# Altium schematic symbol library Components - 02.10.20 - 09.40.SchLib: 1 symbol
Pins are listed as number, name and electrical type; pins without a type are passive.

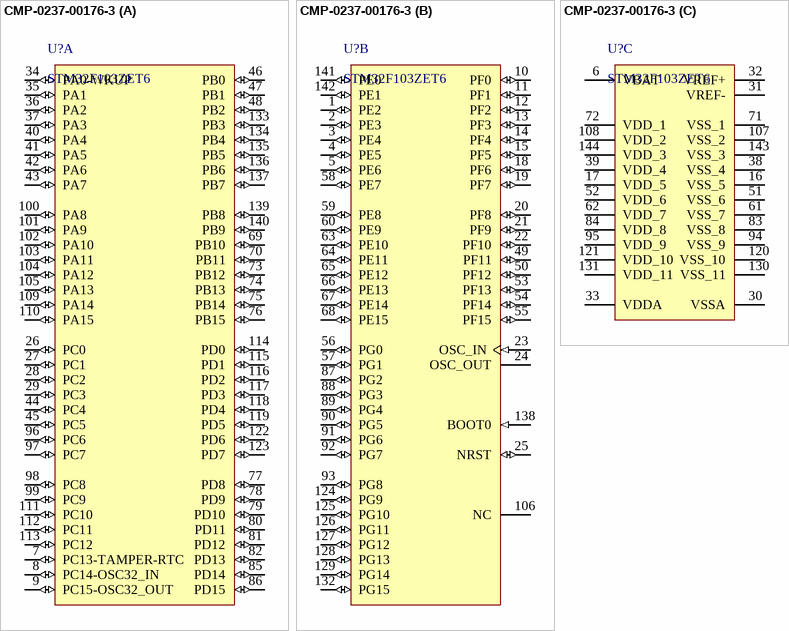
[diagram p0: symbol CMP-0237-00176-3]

## CMP-0237-00176-3
designator U?, comment STM32F103ZET6
ARM Cortex-M3 32-bit MCU, 512 KB Flash, 64 KB Internal RAM, 112 I/Os, 144-pin LQFP, -40 to 85 degC, Tray; D/A Converter: 2x12-bit (2 Channel); FLASH Size (Prog) (kB): 512; Internal RAM Size (kB): 64; I/Os (High Current): 112; Supply Voltage(Vcc) min (V): 2; Operating Frequency(F) (Processor speed) (MHz): 72; A/D Converter: 3x12-bit (21 Channel)
footprint STM-LQFP144_L (Thin QFP, 144-Leads, Body 20x20mm, Pitch 0.5mm, IPC High Density)
footprint STM-LQFP144_M (Thin QFP, 144-Leads, Body 20x20mm, Pitch 0.5mm, IPC Low Density)
footprint STM-LQFP144_N (Thin QFP, 144-Leads, Body 20x20mm, Pitch 0.5mm, IPC Medium Density)
footprint STM-LQFP144_V (Thin QFP, 144-Leads, Body 20x20mm, Pitch 0.5mm, ST Recommended)
part A pins: 7 PC13-TAMPER-RTC (io) "PC13-TAMPER-RTC/PC13/TAMPER-RTC", 8 PC14-OSC32_IN (io) "PC14-OSC32_IN/PC14/OSC32_IN", 9 PC15-OSC32_OUT (io) "PC15-OSC32_OUT/PC15/OSC32_OUT", 26 PC0 (io) "PC0/ADC123_IN10", 27 PC1 (io) "PC1/ADC123_IN11", 28 PC2 (io) "PC2/ADC123_IN12", 29 PC3 (io) "PC3/ADC123_IN13", 34 PA0-WKUP (io) "PA0-WKUP/PA0/WKUP/USART2_CTS/ADC123_IN0/TIM2_CH1_ETR/TIM5_CH1/TIM8_ETR", 35 PA1 (io) "PA1/USART2_RTS/ADC123_IN1/TIM5_CH2/TIM2_CH2", 36 PA2 (io) "PA2/USART2_TX/TIM5_CH3/ADC123_IN2/TIM2_CH3", 37 PA3 (io) "PA3/USART2_RX/TIM5_CH4/ADC123_IN3/TIM2_CH4", 40 PA4 (io) "PA4/SPI1_NSS/USART2_CK/DAC_OUT1/ADC12_IN4", 41 PA5 (io) "PA5/SPI1_SCK/DAC_OUT2/ADC12_IN5", 42 PA6 (io) "PA6/SPI1_MISO/TIM8_BKIN/ADC12_IN6/TIM3_CH1/TIM1_BKIN", 43 PA7 (io) "PA7/SPI1_MOSI/TIM8_CH1N/ADC12_IN7/TIM3_CH2/TIM1_CH1N", 44 PC4 (io) "PC4/ADC12_IN14", 45 PC5 (io) "PC5/ADC12_IN15", 46 PB0 (io) "PB0/ADC12_IN8/TIM3_CH3/TIM8_CH2N/TIM1_CH2N", 47 PB1 (io) "PB1/ADC12_IN9/TIM3_CH4/TIM8_CH3N/TIM1_CH3N", 48 PB2 (io) "PB2/BOOT1", 69 PB10 (io) "PB10/I2C2_SCL/USART3_TX/TIM2_CH3", 70 PB11 (io) "PB11/I2C2_SDA/USART3_RX/TIM2_CH4", 73 PB12 (io) "PB12/SPI2_NSS/I2S2_WS/I2C2_SMBA/USART3_CK/TIM1_BKIN", 74 PB13 (io) "PB13/SPI2_SCK/I2S2_CK/USART3_CTS/TIM1_CH1N", 75 PB14 (io) "PB14/SPI2_MISO/TIM1_CH2N/USART3_RTS", 76 PB15 (io) "PB15/SPI2_MOSI/I2S2_SD/TIM1_CH3N", 77 PD8 (io) "PD8/FSMC_D13/USART3_TX", 78 PD9 (io) "PD9/FSMC_D14/USART3_RX", 79 PD10 (io) "PD10/FSMC_D15/USART3_CK", 80 PD11 (io) "PD11/FSMC_A16/USART3_CTS", 81 PD12 (io) "PD12/FSMC_A17/TIM4_CH1/USART3_RTS", 82 PD13 (io) "PD13/FSMC_A18/TIM4_CH2", 85 PD14 (io) "PD14/FSMC_D0/TIM4_CH3", 86 PD15 (io) "PD15/FSMC_D1/TIM4_CH4", 96 PC6 (io) "PC6/I2S2_MCK/TIM8_CH1/SDIO_D6/TIM3_CH1", 97 PC7 (io) "PC7/I2S3_MCK/TIM8_CH2/SDIO_D7/TIM3_CH2", 98 PC8 (io) "PC8/TIM8_CH3/SDIO_D0/TIM3_CH3", 99 PC9 (io) "PC9/TIM8_CH4/SDIO_D1/TIM3_CH4", 100 PA8 (io) "PA8/USART1_CK/TIM1_CH1/MCO", 101 PA9 (io) "PA9/USART1_TX/TIM1_CH2", 102 PA10 (io) "PA10/USART1_RX/TIM1_CH3", 103 PA11 (io) "PA11/USART1_CTS/USBDM/CAN_RX/TIM1_CH4", 104 PA12 (io) "PA12/USART1_RTS/USBDP/CAN_TX/TIM1_ETR", 105 PA13 (io) "PA13/JTMS-SWDIO", 109 PA14 (io) "PA14/JTCK-SWCLK", 110 PA15 (io) "PA15/JTDI/SPI3_NSS/I2S3_WS/TIM2_CH1_ETR/SPI1_NSS", 111 PC10 (io) "PC10/UART4_TX/SDIO_D2/USART3_TX", 112 PC11 (io) "PC11/UART4_RX/SDIO_D3/USART3_RX", 113 PC12 (io) "PC12/UART5_TX/SDIO_CK/USART3_CK", 114 PD0 (io) "PD0/OSC_IN/FSMC_D2/CAN_RX", 115 PD1 (io) "PD1/OSC_OUT/FSMC_D3/CAN_TX", 116 PD2 (io) "PD2/TIM3_ETR/UART5_RX/SDIO_CMD", 117 PD3 (io) "PD3/FSMC_CLK/USART2_CTS", 118 PD4 (io) "PD4/FSMC_NOE/USART2_RTS", 119 PD5 (io) "PD5/FSMC_NWE/USART2_TX", 122 PD6 (io) "PD6/FSMC_NWAIT/USART2_RX", 123 PD7 (io) "PD7/FSMC_NE1/FSMC_NCE2/USART2_CK", 133 PB3 (io) "PB3/JTDO/SPI3_SCK/I2S3_CK/TRACESWO/TIM2_CH2/SPI1_SCK", 134 PB4 (io) "PB4/NJTRST/SPI3_MISO/TIM3_CH1/SPI1_MISO", 135 PB5 (io) "PB5/I2C1_SMBA/SPI3_MOSI/I2S3_SD/TIM3_CH2/SPI1_MOSI", 136 PB6 (io) "PB6/I2C1_SCL/TIM4_CH1/USART1_TX", 137 PB7 (io) "PB7/I2C1_SDA/FSMC_NADV/TIM4_CH2/USART1_RX", 139 PB8 (io) "PB8/TIM4_CH3/SDIO_D4/I2C1_SCL/CAN_RX", 140 PB9 (io) "PB9/TIM4_CH4/SDIO_D5/I2C1_SDA/CAN_TX"
part B pins: 1 PE2 (io) "PE2/TRACECK/FSMC_A23", 2 PE3 (io) "PE3/TRACED0/FSMC_A19", 3 PE4 (io) "PE4/TRACED1/FSMC_A20", 4 PE5 (io) "PE5/TRACED2/FSMC_A21", 5 PE6 (io) "PE6/TRACED3/FSMC_A22", 10 PF0 (io) "PF0/FSMC_A0", 11 PF1 (io) "PF1/FSMC_A1", 12 PF2 (io) "PF2/FSMC_A2", 13 PF3 (io) "PF3/FSMC_A3", 14 PF4 (io) "PF4/FSMC_A4", 15 PF5 (io) "PF5/FSMC_A5", 18 PF6 (io) "PF6/ADC3_IN4/FSMC_NIORD", 19 PF7 (io) "PF7/ADC3_IN5/FSMC_NREG", 20 PF8 (io) "PF8/ADC3_IN6/FSMC_NIOWR", 21 PF9 (io) "PF9/ADC3_IN7/FSMC_CD", 22 PF10 (io) "PF10/ADC3_IN8/FSMC_INTR", 23 OSC_IN (in), 24 OSC_OUT, 25 NRST (io), 49 PF11 (io) "PF11/FSMC_NIOS16", 50 PF12 (io) "PF12/FSMC_A6", 53 PF13 (io) "PF13/FSMC_A7", 54 PF14 (io) "PF14/FSMC_A8", 55 PF15 (io) "PF15/FSMC_A9", 56 PG0 (io) "PG0/FSMC_A10", 57 PG1 (io) "PG1/FSMC_A11", 58 PE7 (io) "PE7/FSMC_D4/TIM1_ETR", 59 PE8 (io) "PE8/FSMC_D5/TIM1_CH1N", 60 PE9 (io) "PE9/FSMC_D6/TIM1_CH1", 63 PE10 (io) "PE10/FSMC_D7/TIM1_CH2N", 64 PE11 (io) "PE11/FSMC_D8/TIM1_CH2", 65 PE12 (io) "PE12/FSMC_D9/TIM1_CH3N", 66 PE13 (io) "PE13/FSMC_D10/TIM1_CH3", 67 PE14 (io) "PE14/FSMC_D11/TIM1_CH4", 68 PE15 (io) "PE15/FSMC_D12/TIM1_BKIN", 87 PG2 (io) "PG2/FSMC_A12", 88 PG3 (io) "PG3/FSMC_A13", 89 PG4 (io) "PG4/FSMC_A14", 90 PG5 (io) "PG5/FSMC_A15", 91 PG6 (io) "PG6/FSMC_INT2", 92 PG7 (io) "PG7/FSMC_INT3", 93 PG8 (io), 106 NC, 124 PG9 (io) "PG9/FSMC_NE2/FSMC_NCE3", 125 PG10 (io) "PG10/FSMC_NCE4_1/FSMC_NE3", 126 PG11 (io) "PG11/FSMC_NCE4_2", 127 PG12 (io) "PG12/FSMC_NE4", 128 PG13 (io) "PG13/FSMC_A24", 129 PG14 (io) "PG14/FSMC_A25", 132 PG15 (io), 138 BOOT0 (in), 141 PE0 (io) "PE0/TIM4_ETR/FSMC_NBL0", 142 PE1 (io) "PE1/FSMC_NBL1"
part C pins: 6 VBAT (power), 16 VSS_5 (power), 17 VDD_5 (power), 30 VSSA (power), 31 VREF- (power), 32 VREF+ (power), 33 VDDA (power), 38 VSS_4 (power), 39 VDD_4 (power), 51 VSS_6 (power), 52 VDD_6 (power), 61 VSS_7 (power), 62 VDD_7 (power), 71 VSS_1 (power), 72 VDD_1 (power), 83 VSS_8 (power), 84 VDD_8 (power), 94 VSS_9 (power), 95 VDD_9 (power), 107 VSS_2 (power), 108 VDD_2 (power), 120 VSS_10 (power), 121 VDD_10 (power), 130 VSS_11 (power), 131 VDD_11 (power), 143 VSS_3 (power), 144 VDD_3 (power)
